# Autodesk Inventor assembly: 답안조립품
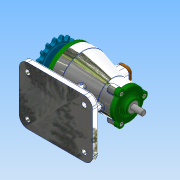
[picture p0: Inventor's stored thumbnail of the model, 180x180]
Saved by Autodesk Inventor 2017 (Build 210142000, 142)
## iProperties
Part Number: 답안조립품
Material: 일반
Document SubType Name: Assembly
Designer: user
Author: user
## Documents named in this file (16)
- C:\Users\user\Desktop\711006V1017\답안조립품.iam
- C:\Users\user\Desktop\711006V1017\본체.ipt
- C:\Users\user\Desktop\711006V1017\마개.ipt
- C:\Users\user\Desktop\711006V1017\앞커버.ipt
- C:\Users\user\Desktop\711006V1017\뒤커버.ipt
- C:\Users\user\Desktop\711006V1017\볼트 M4.ipt
- 볼트 M4 x 12.ipt
- C:\Users\user\Desktop\711006V1017\베어링 6200.ipt
- C:\Users\user\Desktop\711006V1017\베어링 6203.ipt
- C:\Users\user\Desktop\711006V1017\오일 실 17x30x8.ipt
- C:\Users\user\Desktop\711006V1017\오일 실 10x20x7.ipt
- C:\Users\user\Desktop\711006V1017\축.ipt
- C:\Users\user\Desktop\711006V1017\키 5x5.ipt
- 키 5 x 5.ipt
- C:\Users\user\Desktop\711006V1017\스프로킷.ipt
- C:\Users\user\Desktop\711006V1017\와셔.ipt
